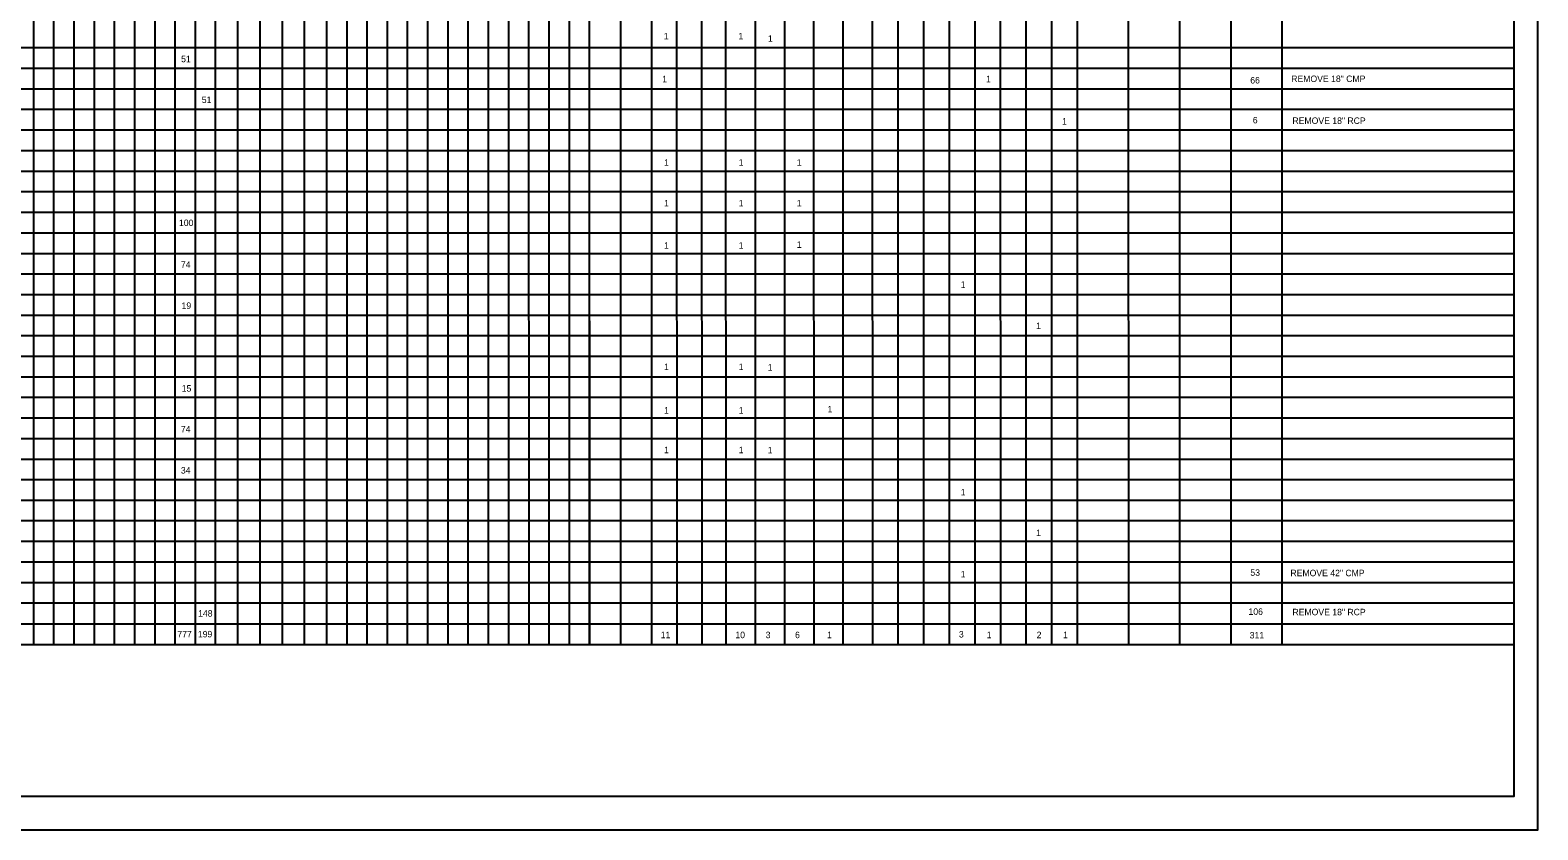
# Model space of a CAD drawing. Extents: x 809447 to 814738, y 647528 to 651206.
# Drawn here: x 811820 to 812939, y 650017 to 650610 of the extents above; entities that cross this region are included whole.
import ezdxf

# ---------------------------------------------------------------- set-up
doc = ezdxf.new("R2010")
doc.units = 0
doc.layers.add('Default', color=7, linetype='Continuous')

msp = doc.modelspace()

# ---------------------------------------------------------------- linework, layer by layer
at = {"layer": 'Default'}
for p, q in [((811822.5, 650154.3), (811822.5, 650925)), ((811927.5, 650154.3), (811927.5, 650925)), ((812040.1, 650154.3), (812040, 650925.1)), ((812160.1, 650154.3), (812160, 650925.1)), ((812175.1, 650154.3), (812175, 650925.1)), ((812190.1, 650154.3), (812190, 650925.1)), ((812205.1, 650154.3), (812205, 650925.1)), ((812220.1, 650154.3), (812220, 650925.1)), ((812235.1, 650154.3), (812235, 650925.1)), ((812235, 650154.3), (812235, 650925.1)), ((812235.1, 650154.3), (812235, 650925.1)), ((812281.3, 650154.3), (812281.2, 650925)), ((812336.3, 650154.3), (812336.2, 650925)), ((812336.3, 650154.3), (812336.2, 650925)), ((812358.1, 650154.3), (812358.1, 650925)), ((812445.1, 650154.3), (812445, 650925)), ((812483.1, 650154.3), (812483, 650925)), ((812502.1, 650154.3), (812502, 650925)), ((812521.1, 650154.3), (812521, 650925)), ((812540.1, 650154.3), (812540, 650925)), ((812559.1, 650154.3), (812559, 650925)), ((812578.1, 650154.3), (812578, 650925)), ((812597.1, 650154.3), (812597, 650925)), ((812635.1, 650154.3), (812635, 650925)), ((812635.1, 650154.3), (812635, 650925)), ((812673.1, 650154.3), (812673, 650925)), ((812673.1, 650154.3), (812673, 650925)), ((812711.1, 650154.3), (812711, 650925)), ((812711.1, 650154.3), (812711, 650925)), ((812749.1, 650154.3), (812749, 650925)), ((812749.1, 650154.3), (812749, 650925)), ((812299.9, 650154.3), (812299.8, 650834.3)), ((812464.1, 650154.3), (812464, 650834.3)), ((811837.5, 650154.3), (811837.5, 650817.1)), ((811852.5, 650154.3), (811852.5, 650817.2)), ((811867.5, 650154.3), (811867.5, 650817.1)), ((811882.5, 650154.3), (811882.5, 650817.2)), ((811897.5, 650154.3), (811897.5, 650817.1)), ((811912.5, 650154.3), (811912.5, 650817.2)), ((811927.5, 650154.3), (811927.5, 650817.1)), ((811942.5, 650154.3), (811942.5, 650817.2)), ((811957.5, 650154.3), (811957.5, 650817.2)), ((811974, 650154.3), (811974, 650817.2)), ((811990.5, 650154.3), (811990.5, 650817.2)), ((812007, 650154.3), (812007, 650817.2)), ((812023.5, 650154.3), (812023.5, 650817.2)), ((812040, 650154.3), (812040, 650817.2)), ((812055, 650154.3), (812055, 650817.2)), ((812070, 650154.3), (812070, 650817.2)), ((812085, 650154.3), (812085, 650817.2)), ((812100, 650154.3), (812100, 650817.2)), ((812115, 650154.3), (812115, 650817.2)), ((812130, 650154.3), (812130, 650817.2)), ((812145, 650154.3), (812145, 650817.2)), ((812160, 650154.3), (812160, 650817.2)), ((812318.5, 650154.3), (812318.4, 650811.1)), ((811822.5, 650154.3), (811822.5, 650791.8)), ((812258.2, 650154.3), (812258.1, 650791.8)), ((812379.9, 650154.3), (812379.8, 650749)), ((812401.6, 650154.3), (812401.5, 650749)), ((812423.3, 650154.3), (812423.3, 650749)), ((812921.2, 650597.3), (811421.2, 650597.3)), ((812921.2, 650582), (811421.2, 650582)), ((812921.2, 650566.7), (811421.2, 650566.7)), ((812921.2, 650551.5), (811421.2, 650551.5)), ((812921.2, 650536.2), (811421.2, 650536.2)), ((812921.2, 650520.9), (811421.2, 650520.9)), ((812921.2, 650505.6), (811421.2, 650505.6)), ((812921.2, 650490.4), (811421.2, 650490.4)), ((812921.2, 650475.1), (811421.2, 650475.1)), ((812921.2, 650459.8), (811421.2, 650459.8)), ((812921.2, 650444.5), (811421.2, 650444.5)), ((812921.2, 650429.3), (811421.2, 650429.3)), ((812921.2, 650414), (811421.2, 650414)), ((812921.2, 650398.8), (811421.2, 650398.8)), ((812921.2, 650383.5), (811421.2, 650383.5)), ((812921.2, 650368.3), (811421.2, 650368.3)), ((812921.2, 650353), (811421.2, 650353)), ((812921.2, 650337.8), (811421.2, 650337.8)), ((812921.2, 650322.5), (811421.2, 650322.5)), ((812921.2, 650307.2), (811421.2, 650307.2)), ((812921.2, 650291.9), (811421.2, 650291.9)), ((812921.2, 650276.7), (811421.2, 650276.7)), ((812921.2, 650261.4), (811421.2, 650261.4)), ((812921.2, 650246.2), (811421.2, 650246.2)), ((812921.2, 650230.9), (811421.2, 650230.9)), ((812921.2, 650215.7), (811421.2, 650215.7)), ((812921.2, 650200.4), (811421.2, 650200.4)), ((812921.2, 650185.2), (811421.2, 650185.2)), ((812921.2, 650169.6), (811421.2, 650169.6)), ((812921.2, 650154.3), (811421.2, 650154.3)), ((812921.2, 650154.3), (811421.2, 650154.3))]:
    msp.add_line(p, q, dxfattribs=at)
for points in [[(812938.7, 651116.9), (811254.7, 651116.9), (811254.7, 650016.9), (812938.7, 650016.9)], [(812921.2, 651091.9), (811421.2, 651091.9), (811421.2, 650041.9), (812921.2, 650041.9)]]:
    msp.add_lwpolyline(points, close=True, dxfattribs=at)

# ---------------------------------------------------------------- texts
for s, p in [('1', (812290.1, 650603.7)), ('1', (812345.5, 650603.7)), ('1', (812367.4, 650601.9)), ('51', (811931.9, 650586.7)), ('1', (812288.9, 650571.8)), ('1', (812529.2, 650571.8)), ('66', (812725.3, 650570.9)), ('REMOVE 18" CMP', (812755.7, 650572)), ('51', (811947.2, 650556.4)), ('1', (812585.6, 650540.4)), ('6', (812727.2, 650541.3)), ('REMOVE 18" RCP', (812756.6, 650540.9)), ('1', (812290.3, 650509.9)), ('1', (812345.7, 650509.9)), ('1', (812388.8, 650509.9)), ('1', (812290.3, 650479.7)), ('1', (812345.7, 650479.7)), ('1', (812388.8, 650479.7)), ('100', (811930.3, 650465.1)), ('1', (812290.3, 650448.3)), ('1', (812345.7, 650448.3)), ('1', (812388.8, 650448.9)), ('74', (811931.7, 650434.1)), ('1', (812510.4, 650419.2)), ('19', (811932.2, 650403.6)), ('1', (812566.4, 650388.7)), ('1', (812290.3, 650358.2)), ('1', (812345.7, 650358.2)), ('1', (812367.2, 650357.8)), ('15', (811932.3, 650342.2)), ('1', (812290.3, 650325.9)), ('1', (812345.7, 650325.9)), ('1', (812411.6, 650326.8)), ('74', (811931.7, 650311.9)), ('1', (812290.3, 650296.5)), ('1', (812345.7, 650296.5)), ('1', (812367.2, 650296.4)), ('34', (811931.7, 650281.4)), ('1', (812510.4, 650265.1)), ('1', (812566.4, 650235)), ('1', (812510.4, 650204.3)), ('53', (812725.4, 650205.5)), ('REMOVE 42" CMP', (812755.1, 650205.2)), ('148', (811944.5, 650175.2)), ('106', (812724, 650176.5)), ('REMOVE 18" RCP', (812756.6, 650176.2)), ('777', (811929.1, 650159.8)), ('199', (811944.3, 650159.8)), ('11', (812287.8, 650159.2)), ('10', (812343.2, 650159.2)), ('3', (812365.7, 650159.2)), ('6', (812387.5, 650159.2)), ('1', (812411.2, 650159.2)), ('3', (812509.1, 650159.7)), ('1', (812529.7, 650159.2)), ('2', (812566.8, 650159.2)), ('1', (812586.4, 650159.2)), ('311', (812724.9, 650159))]:
    msp.add_text(s, height=4.8, dxfattribs=at).set_placement(p)

doc.saveas('drawing.dxf')
